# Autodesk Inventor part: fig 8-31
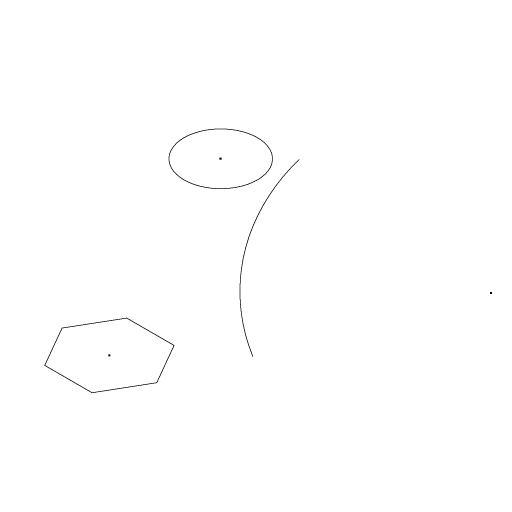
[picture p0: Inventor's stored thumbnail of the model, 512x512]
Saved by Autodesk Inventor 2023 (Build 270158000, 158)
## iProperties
Created: 2001-12
Part Number: fig 8-31
Document SubType Name: Modeling
Designer: CADSoft
Density: 1 g/cm^3
Material: Generic
Appearance: Default
Control State: 0
Master: False
Checked Out: False
Shininess: 77.0
Angle Display Precision: 2
Document Length Units: 11269
Document Angle Units: 11279
Document Time Units: 11290
Document Mass Units: 11283
Document Length Units Precision: 3
Document Angle Units Precision: 2
Density: 0.0
Volumn: 0.0
Area: 0.0
PropertySet Name: Model Information
Author: CADSoft
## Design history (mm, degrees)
workplane "Work Plane3"
workplane "Work Plane4"
sketch "Sketch12"
  geometry: L1 (0, 10.598)-(9.178, -5.299); L2 (9.178, -5.299)-(-9.178, -5.299); L3 (-9.178, -5.299)-(0, 10.598); 1 further point
  constraints: 6 end point, 5 other
workplane "Work Plane5"
workplane "Work Plane6"
workplane "Work Plane7"
sketch "Sketch16"
  geometry: A1 r 72.799 centre (23.007, 110.594) between (0, 41.527) and (70, 54.995); 1 further point
  constraints: 2 point on circle, 1 centre point
body "Solid1"
sketch "Sketch1"
  geometry: L1 (19.387, 0)-(9.693, -16.79); L2 (9.693, -16.79)-(-9.693, -16.79); L3 (-9.693, -16.79)-(-19.387, 0); L4 (-19.387, 0)-(-9.693, 16.79); L5 (-9.693, 16.79)-(9.693, 16.79); L6 (9.693, 16.79)-(19.387, 0); 1 further point
  constraints: 12 end point, 11 other
sketch "Sketch2"
  geometry: C1 r 15 at (23.06, 22.535)
  constraints: 1 centre point
